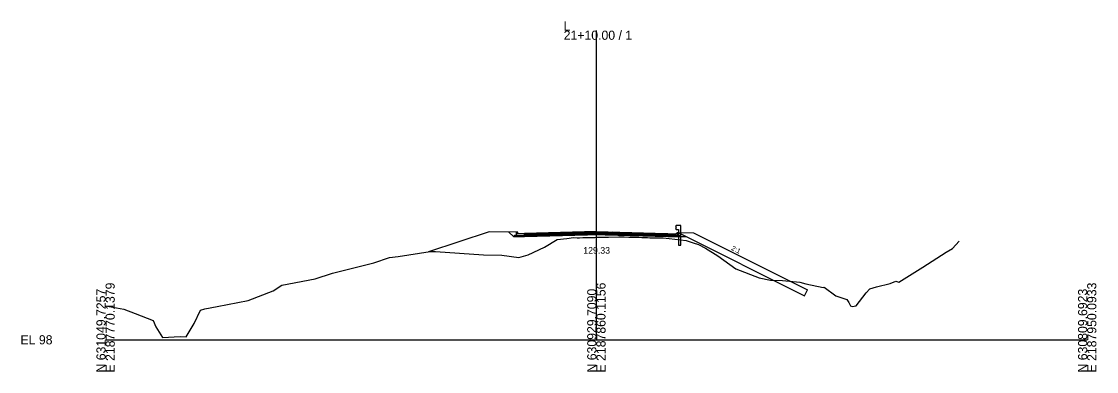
# Model space of a CAD drawing. Extents: x -26 to 4903, y -1010 to 9587.
# Drawn here: x 4574.3 to 4902.8, y -1009.7 to -902.7 of the extents above; entities that cross this region are included whole.
import ezdxf

# ---------------------------------------------------------------- set-up
doc = ezdxf.new("R2010")
doc.units = 0
for name, color, linetype in [('Default', 7, 'Continuous'), ('Exist Cross Section Cell', 7, 'Continuous'), ('Exist XS Center Line Elevation Label', 7, 'Continuous'), ('Exist XS Ground Line', 7, 'Continuous'), ('Prop CMT Conc Surface', 7, 'Continuous'), ('Prop CMT Concrete Structures', 7, 'Continuous'), ('Prop CMT Guardrail SBG', 7, 'Continuous'), ('Prop CMT Pvmt Course 1', 7, 'Continuous'), ('Prop CMT Pvmt Course 1 CG', 7, 'Continuous'), ('Prop CMT Pvmt Course 1 Wedge', 7, 'Continuous'), ('Prop CMT Pvmt Course 2', 7, 'Continuous'), ('Prop CMT Pvmt Course 2 Wedge', 7, 'Continuous'), ('Prop CMT Pvmt Course 3', 7, 'Continuous'), ('Prop CMT Pvmt Course 3 Wedge', 7, 'Continuous'), ('Prop CMT Pvmt Course SBG', 7, 'Continuous'), ('Prop CMT Pvmt Surface', 7, 'Continuous'), ('Prop CMT Pvmt Surface Shoulder', 7, 'Continuous'), ('Prop CMT Pvmt Wedge Surface 1', 7, 'Continuous'), ('Prop CMT Pvmt Wedge Surface 2', 7, 'Continuous'), ('Prop CMT Pvmt Wedge Surface 3', 7, 'Continuous'), ('Prop CMT Shld Paved Course 1', 7, 'Continuous'), ('Prop CMT Shld Paved Course 2', 7, 'Continuous'), ('Prop CMT Shld Paved Course 3', 7, 'Continuous'), ('Prop CMT Slope Grass', 7, 'Continuous'), ('Prop CMT Subgrade Earthwork', 7, 'Continuous'), ('Prop XS Class II Rip Rap Ditch Liner', 7, 'Continuous'), ('Prop XS Side Slope Text', 7, 'Continuous')]:
    doc.layers.add(name, color=color, linetype=linetype)

msp = doc.modelspace()

# ---------------------------------------------------------------- linework, layer by layer
at = {"layer": 'Exist Cross Section Cell'}
for p, q in [((4750, -1000), (4750, -905.49)), ((4600, -1000), (4750, -1000)), ((4750, -1000), (4900, -1000))]:
    msp.add_line(p, q, dxfattribs=at)
at = {"layer": 'Exist XS Ground Line'}
for p, q in [((4738.04, -969.32), (4740.93, -969.04)), ((4740.93, -969.04), (4742.99, -968.76)), ((4742.99, -968.76), (4744.14, -968.81)), ((4744.14, -968.81), (4744.48, -968.81)), ((4744.48, -968.81), (4744.88, -968.8)), ((4744.88, -968.8), (4745.86, -968.77)), ((4745.86, -968.77), (4747.56, -968.74)), ((4747.56, -968.74), (4747.96, -968.73)), ((4747.96, -968.73), (4749.52, -968.68)), ((4749.52, -968.68), (4750, -968.67)), ((4750, -968.67), (4750.64, -968.65)), ((4750.64, -968.65), (4751.31, -968.63)), ((4751.31, -968.63), (4752.24, -968.61)), ((4752.24, -968.61), (4753.72, -968.58)), ((4753.72, -968.58), (4756.84, -968.5)), ((4756.84, -968.5), (4756.91, -968.54)), ((4756.91, -968.54), (4757.86, -968.52)), ((4757.86, -968.52), (4758.47, -968.54)), ((4758.47, -968.54), (4759.88, -968.58)), ((4759.88, -968.58), (4760.8, -968.61)), ((4760.8, -968.61), (4762.96, -968.67)), ((4762.96, -968.67), (4763.85, -968.7)), ((4763.85, -968.7), (4765.08, -968.75)), ((4765.08, -968.75), (4765.64, -968.77)), ((4765.64, -968.77), (4766.33, -968.79)), ((4766.33, -968.79), (4767.82, -968.82)), ((4767.82, -968.82), (4769.22, -968.87)), ((4769.22, -968.87), (4770.44, -968.87)), ((4770.44, -968.87), (4772.24, -969.05)), ((4772.24, -969.05), (4777.47, -969.61)), ((4729.14, -974.02), (4734.18, -971.66)), ((4734.18, -971.66), (4738.04, -969.32)), ((4777.47, -969.61), (4778.32, -969.91)), ((4778.32, -969.91), (4779.55, -970.37)), ((4779.55, -970.37), (4781.18, -970.88)), ((4781.18, -970.88), (4783.37, -972.02)), ((4783.37, -972.02), (4787.13, -974.28)), ((4856.87, -973.22), (4858.79, -972.04)), ((4858.79, -972.04), (4860.82, -969.81)), ((4681.98, -976.45), (4686.77, -974.88)), ((4686.77, -974.88), (4689.4, -974.52)), ((4689.4, -974.52), (4699.17, -973.05)), ((4699.17, -973.05), (4700.19, -972.97)), ((4700.19, -972.97), (4700.79, -972.96)), ((4700.79, -972.96), (4715.53, -974.02)), ((4715.53, -974.02), (4721.12, -974.15)), ((4721.12, -974.15), (4726.28, -974.82)), ((4726.28, -974.82), (4729.14, -974.02)), ((4787.13, -974.28), (4792.57, -978.33)), ((4849.81, -977.84), (4856.87, -973.22)), ((4669.35, -979.6), (4672.57, -978.85)), ((4672.57, -978.85), (4681.98, -976.45)), ((4792.57, -978.33), (4799.7, -981.04)), ((4842.39, -982.37), (4849.81, -977.84)), ((4653.82, -983.33), (4664.04, -981.36)), ((4664.04, -981.36), (4669.35, -979.6)), ((4799.7, -981.04), (4803.25, -981.81)), ((4803.25, -981.81), (4806.89, -981.9)), ((4806.89, -981.9), (4812.16, -982.39)), ((4839.8, -982.79), (4841.55, -982.11)), ((4841.55, -982.11), (4842.39, -982.37)), ((4643.53, -988.03), (4651.22, -984.98)), ((4651.22, -984.98), (4653.82, -983.33)), ((4812.16, -982.39), (4814, -982.91)), ((4814, -982.91), (4819.33, -984.04)), ((4819.33, -984.04), (4819.64, -983.95)), ((4819.64, -983.95), (4823.18, -986.57)), ((4832.48, -985.66), (4833.55, -984.42)), ((4833.55, -984.42), (4835.59, -983.84)), ((4835.59, -983.84), (4839.8, -982.79)), ((4634.06, -989.82), (4643.53, -988.03)), ((4823.18, -986.57), (4826.49, -987.65)), ((4826.49, -987.65), (4827.12, -988.6)), ((4827.12, -988.6), (4827.69, -989.65)), ((4829.42, -989.58), (4832.48, -985.66)), ((4600, -989.62), (4605.63, -990.67)), ((4605.63, -990.67), (4609.09, -991.96)), ((4609.09, -991.96), (4614.57, -994.11)), ((4627.03, -994.99), (4628.99, -990.9)), ((4628.99, -990.9), (4630.38, -990.55)), ((4630.38, -990.55), (4634.06, -989.82)), ((4827.69, -989.65), (4828.12, -989.77)), ((4828.12, -989.77), (4829.42, -989.58)), ((4614.57, -994.11), (4615.39, -996.01)), ((4624.65, -999.08), (4627.03, -994.99)), ((4615.39, -996.01), (4617.37, -999.3)), ((4617.37, -999.3), (4622.82, -999.01)), ((4622.82, -999.01), (4624.65, -999.08))]:
    msp.add_line(p, q, dxfattribs=at)
at = {"layer": 'Prop CMT Conc Surface'}
for p, q in [((4726, -967.11), (4725.5, -967.11)), ((4726, -967.61), (4726, -967.11)), ((4728, -967.48), (4726, -967.61)), ((4771.82, -967.48), (4774.15, -967.57)), ((4774.15, -967.57), (4774.82, -967.23))]:
    msp.add_line(p, q, dxfattribs=at)
at = {"layer": 'Prop CMT Concrete Structures'}
for p, q in [((4726, -967.11), (4725.5, -967.11)), ((4725.5, -967.11), (4725.5, -968.13)), ((4725.5, -968.13), (4728, -968.06)), ((4726, -967.61), (4726, -967.11)), ((4728, -967.48), (4726, -967.61)), ((4728, -968.06), (4728, -967.48)), ((4771.82, -967.48), (4774.15, -967.57)), ((4771.82, -968.06), (4771.82, -967.48)), ((4774.82, -968.06), (4771.82, -968.06)), ((4774.15, -967.57), (4774.82, -967.23)), ((4774.82, -967.23), (4774.82, -968.06))]:
    msp.add_line(p, q, dxfattribs=at)
at = {"layer": 'Prop CMT Guardrail SBG'}
for p, q in [((4774.42, -965.07), (4774.15, -965.36)), ((4774.15, -965.36), (4774.42, -965.65)), ((4774.42, -965.65), (4774.15, -965.94)), ((4775.76, -965.07), (4774.42, -965.07)), ((4775.76, -971.07), (4775.76, -965.07)), ((4774.15, -965.94), (4774.42, -966.24)), ((4774.42, -966.24), (4775.09, -966.24)), ((4775.09, -966.24), (4775.09, -971.07)), ((4775.09, -971.07), (4775.76, -971.07))]:
    msp.add_line(p, q, dxfattribs=at)
at = {"layer": 'Prop CMT Pvmt Course 1'}
for p, q in [((4750, -966.93), (4728, -967.48)), ((4728, -967.73), (4755, -967.06)), ((4728, -967.48), (4728, -967.73)), ((4768, -967.63), (4745, -967.06)), ((4745, -967.06), (4745, -967.06)), ((4745, -967.06), (4745, -967.06)), ((4745, -967.06), (4750, -967.18)), ((4750, -967.18), (4750, -966.93)), ((4750, -966.93), (4768, -967.38)), ((4750, -967.18), (4750, -966.93)), ((4755, -967.06), (4750, -967.18)), ((4755, -967.06), (4755, -967.06)), ((4755, -967.06), (4755, -967.06)), ((4768, -967.38), (4768, -967.63)), ((4768, -967.38), (4768, -967.63))]:
    msp.add_line(p, q, dxfattribs=at)
at = {"layer": 'Prop CMT Pvmt Course 1 CG'}
for p, q in [((4725, -968.14), (4724.67, -968.47)), ((4724.67, -968.47), (4728, -968.39)), ((4728, -968.06), (4725, -968.14)), ((4728, -968.39), (4728, -968.06))]:
    msp.add_line(p, q, dxfattribs=at)
at = {"layer": 'Prop CMT Pvmt Course 1 Wedge'}
for p, q in [((4745, -967.06), (4745, -967.06)), ((4755, -967.06), (4755, -967.06))]:
    msp.add_line(p, q, dxfattribs=at)
at = {"layer": 'Prop CMT Pvmt Course 2'}
for p, q in [((4755, -967.06), (4728, -967.73)), ((4728, -968.06), (4755, -967.39)), ((4728, -967.73), (4728, -968.06)), ((4745, -967.06), (4745, -967.39)), ((4750, -967.18), (4745, -967.06)), ((4745, -967.39), (4745, -967.06)), ((4745, -967.06), (4768, -967.63)), ((4745, -967.39), (4750, -967.51)), ((4768, -967.96), (4745, -967.39)), ((4750, -967.18), (4755, -967.06)), ((4750, -967.51), (4750, -967.18)), ((4750, -967.51), (4750, -967.18)), ((4755, -967.39), (4750, -967.51)), ((4755, -967.06), (4755, -967.39)), ((4755, -967.39), (4755, -967.06)), ((4768, -967.63), (4768, -967.96)), ((4768, -967.63), (4768, -967.96))]:
    msp.add_line(p, q, dxfattribs=at)
at = {"layer": 'Prop CMT Pvmt Course 2 Wedge'}
for p, q in [((4745, -967.06), (4745, -967.06)), ((4755, -967.06), (4755, -967.06))]:
    msp.add_line(p, q, dxfattribs=at)
at = {"layer": 'Prop CMT Pvmt Course 3'}
for p, q in [((4755, -967.39), (4728, -968.06)), ((4728, -968.39), (4755, -967.72)), ((4728, -968.06), (4728, -968.39)), ((4750, -967.51), (4745, -967.39)), ((4745, -967.39), (4745, -967.72)), ((4745, -967.39), (4768, -967.96)), ((4745, -967.72), (4745, -967.39)), ((4745, -967.72), (4750, -967.84)), ((4768, -968.29), (4745, -967.72)), ((4750, -967.51), (4755, -967.39)), ((4750, -967.84), (4750, -967.51)), ((4750, -967.84), (4750, -967.51)), ((4755, -967.72), (4750, -967.84)), ((4755, -967.39), (4755, -967.72)), ((4755, -967.72), (4755, -967.39)), ((4768, -967.96), (4768, -968.29)), ((4768, -967.96), (4768, -968.29))]:
    msp.add_line(p, q, dxfattribs=at)
at = {"layer": 'Prop CMT Pvmt Course 3 Wedge'}
for p, q in [((4745, -967.39), (4745, -967.39)), ((4755, -967.39), (4755, -967.39))]:
    msp.add_line(p, q, dxfattribs=at)
at = {"layer": 'Prop CMT Pvmt Course SBG'}
for p, q in [((4771.82, -968.14), (4771.82, -967.89)), ((4771.82, -968.06), (4774.82, -968.06)), ((4775.32, -968.06), (4771.82, -968.06)), ((4774.82, -968.06), (4775.32, -968.06)), ((4775.32, -968.06), (4775.65, -968.39))]:
    msp.add_line(p, q, dxfattribs=at)
at = {"layer": 'Prop CMT Pvmt Surface'}
for q in [(4728, -967.48), (4768, -967.38)]:
    msp.add_line((4750, -966.93), q, dxfattribs=at)
at = {"layer": 'Prop CMT Pvmt Surface Shoulder'}
msp.add_line((4768, -967.38), (4771.82, -967.48), dxfattribs=at)
at = {"layer": 'Prop CMT Pvmt Wedge Surface 1'}
for p, q in [((4755, -967.06), (4728, -967.73)), ((4728, -967.73), (4728, -967.48)), ((4745, -967.06), (4745, -967.06)), ((4745, -967.06), (4745, -967.06)), ((4745, -967.06), (4768, -967.63)), ((4750, -967.18), (4745, -967.06)), ((4745, -967.06), (4745, -967.06)), ((4750, -966.93), (4750, -967.18)), ((4750, -966.93), (4750, -967.18)), ((4750, -967.18), (4755, -967.06)), ((4755, -967.06), (4755, -967.06)), ((4755, -967.06), (4755, -967.06)), ((4755, -967.06), (4755, -967.06)), ((4768, -967.63), (4768, -967.38)), ((4768, -967.63), (4768, -967.38))]:
    msp.add_line(p, q, dxfattribs=at)
at = {"layer": 'Prop CMT Pvmt Wedge Surface 2'}
for p, q in [((4755, -967.06), (4728, -967.73)), ((4728, -967.73), (4728, -967.48)), ((4745, -967.06), (4768, -967.63)), ((4750, -967.18), (4745, -967.06)), ((4750, -966.93), (4750, -967.18)), ((4750, -966.93), (4750, -967.18)), ((4750, -967.18), (4755, -967.06)), ((4768, -967.63), (4768, -967.38)), ((4768, -967.63), (4768, -967.38))]:
    msp.add_line(p, q, dxfattribs=at)
at = {"layer": 'Prop CMT Pvmt Wedge Surface 3'}
for p, q in [((4755, -967.39), (4728, -968.06)), ((4728, -968.06), (4728, -967.48)), ((4745, -967.39), (4768, -967.96)), ((4750, -967.51), (4745, -967.39)), ((4750, -966.93), (4750, -967.51)), ((4750, -966.93), (4750, -967.51)), ((4750, -967.51), (4755, -967.39)), ((4768, -967.96), (4768, -967.38)), ((4768, -967.96), (4768, -967.38))]:
    msp.add_line(p, q, dxfattribs=at)
at = {"layer": 'Prop CMT Shld Paved Course 1'}
for p, q in [((4768, -967.63), (4768, -967.38)), ((4768, -967.38), (4771.82, -967.48)), ((4768, -967.63), (4768, -967.38)), ((4771.82, -967.73), (4768, -967.63)), ((4771.82, -967.48), (4771.82, -967.73))]:
    msp.add_line(p, q, dxfattribs=at)
at = {"layer": 'Prop CMT Shld Paved Course 2'}
for p, q in [((4768, -967.96), (4768, -967.63)), ((4768, -967.63), (4771.82, -967.73)), ((4768, -967.96), (4768, -967.63)), ((4771.82, -968.06), (4768, -967.96)), ((4771.82, -967.73), (4771.82, -968.06))]:
    msp.add_line(p, q, dxfattribs=at)
at = {"layer": 'Prop CMT Shld Paved Course 3'}
for p, q in [((4768, -967.96), (4771.82, -968.06)), ((4768, -968.29), (4768, -967.96)), ((4771.82, -968.39), (4768, -968.29)), ((4771.82, -968.06), (4771.82, -968.39))]:
    msp.add_line(p, q, dxfattribs=at)
at = {"layer": 'Prop CMT Slope Grass'}
for p, q in [((4717.21, -966.95), (4698.69, -973.12)), ((4725.5, -967.11), (4717.21, -966.95)), ((4774.82, -967.23), (4774.99, -967.23)), ((4779.65, -967.32), (4809.25, -982.12))]:
    msp.add_line(p, q, dxfattribs=at)
at = {"layer": 'Prop CMT Subgrade Earthwork'}
for p, q in [((4724.67, -968.47), (4723.26, -967.07)), ((4728, -968.39), (4724.67, -968.47)), ((4755, -967.72), (4728, -968.39)), ((4750, -967.84), (4745, -967.72)), ((4745, -967.72), (4768, -968.29)), ((4750, -967.84), (4755, -967.72)), ((4768, -968.29), (4771.82, -968.39)), ((4771.82, -968.39), (4775.57, -968.39)), ((4775.57, -968.39), (4777.31, -968.39))]:
    msp.add_line(p, q, dxfattribs=at)
at = {"layer": 'Prop XS Class II Rip Rap Ditch Liner'}
for p, q in [((4774.99, -967.23), (4813.63, -986.55)), ((4774.99, -967.23), (4779.65, -967.32)), ((4809.25, -982.12), (4814.53, -984.76)), ((4813.63, -986.55), (4814.53, -984.76))]:
    msp.add_line(p, q, dxfattribs=at)

# ---------------------------------------------------------------- texts
at = {"layer": 'Default'}
msp.add_text('-', height=0.0001, dxfattribs=at).set_placement((4600, -1000))
at = {"layer": 'Exist Cross Section Cell'}
for s, p in [('L', (4740, -905.49)), ('21+10.00 / 1', (4740, -908.29)), ('EL 98', (4574, -1001.4))]:
    msp.add_text(s, height=2.8, dxfattribs=at).set_placement(p)
for s, p in [('N 631049.7257', (4600, -1010)), ('E 2187770.1379', (4602.8, -1010)), ('N 630929.7090', (4750, -1010)), ('E 2187860.1156', (4752.8, -1010)), ('N 630809.6923', (4900, -1010)), ('E 2187950.0933', (4902.8, -1010))]:
    msp.add_text(s, height=2.8, rotation=90, dxfattribs=at).set_placement(p)
at = {"layer": 'Exist XS Center Line Elevation Label'}
msp.add_text('129.33', height=2, dxfattribs=at).set_placement((4745.99, -973.67))
at = {"layer": 'Prop XS Side Slope Text'}
msp.add_text('2:1', height=1.5, rotation=333.4349, dxfattribs=at).set_placement((4791.08, -972.47))

doc.saveas('drawing.dxf')
